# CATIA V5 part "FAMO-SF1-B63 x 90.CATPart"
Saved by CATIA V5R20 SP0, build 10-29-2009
Part number: FAMO-SF1-B63 x 90
Definition: NONE
Nomenclature: FAMO-SF1-B63 x 90
Source: Unknown
Description: FAMO-SF1-B63 x 90
Bounding box of the stored display mesh (mm): x -13 to 77, y -46 to 46, z -46 to 46
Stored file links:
  C:\Users\Utente\Desktop\IO LAVORO\3D X SITO CF\X SITO\FAMO\FAMO-SF1-B63 x 90.CATPart

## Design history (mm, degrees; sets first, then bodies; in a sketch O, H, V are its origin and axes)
Body1 "FAMO-SF1-B63 x 90" (main body)
  Solid1: solid without history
